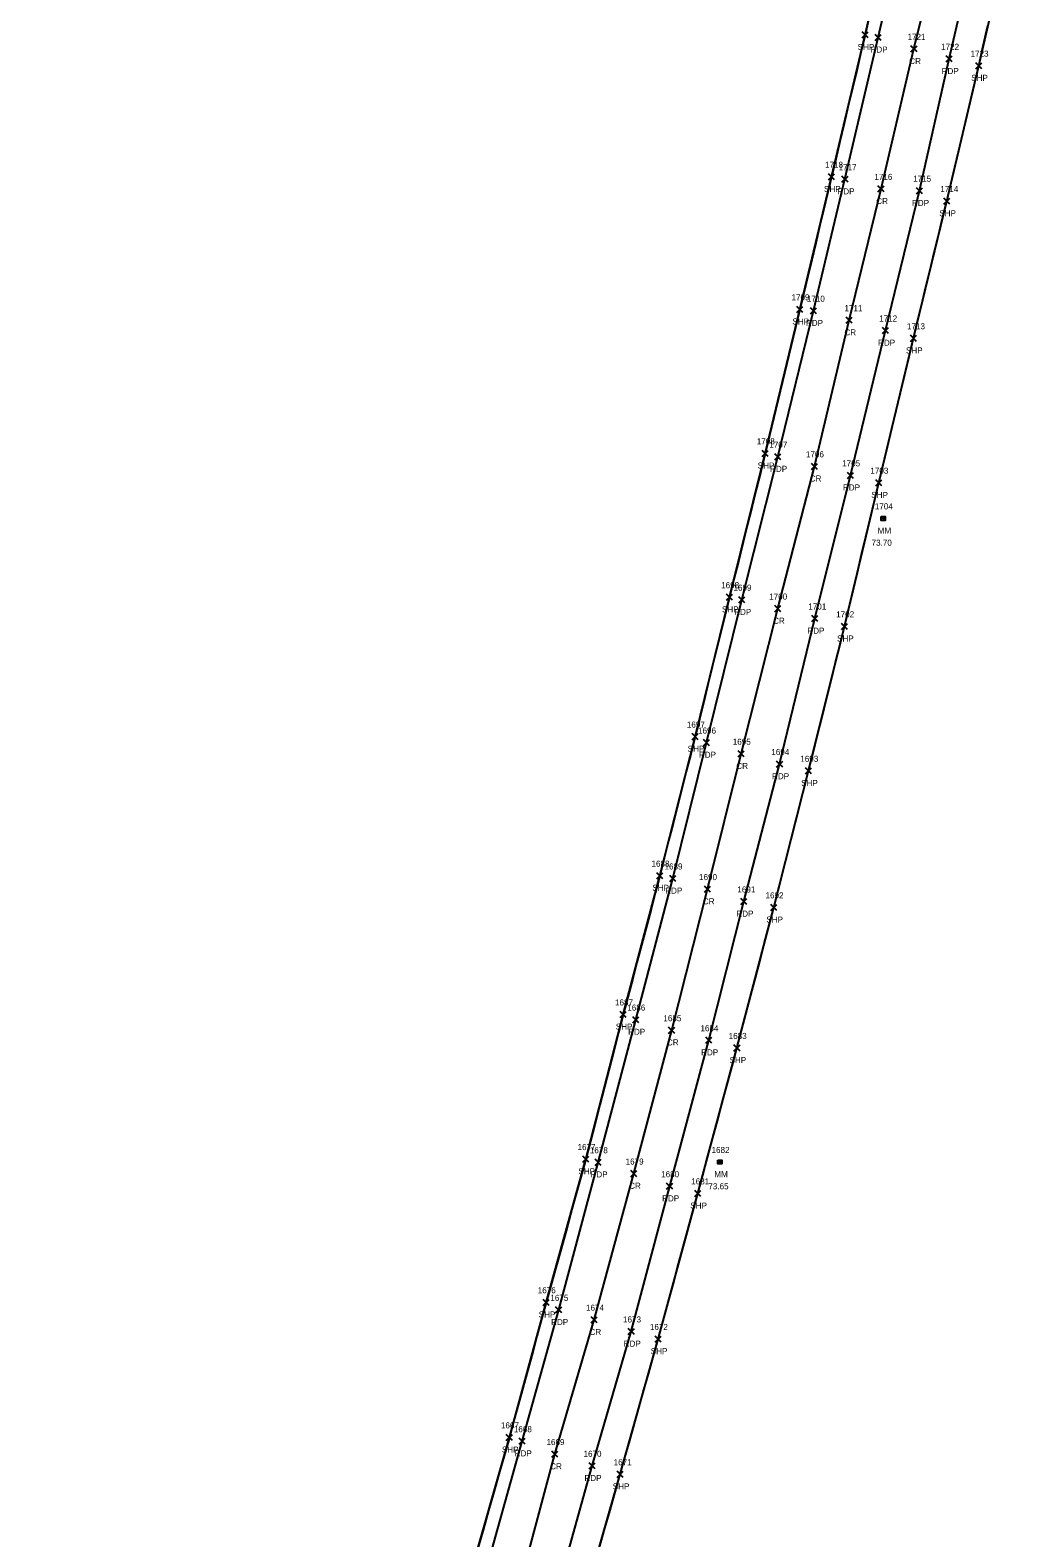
# Model space of a CAD drawing. Extents: x 1688195 to 1692013, y 424605 to 441234.
# Drawn here: x 1690035.6 to 1690361.3, y 433631 to 434129.2 of the extents above; entities that cross this region are included whole.
import ezdxf

# ---------------------------------------------------------------- set-up
doc = ezdxf.new("R2010")
doc.units = 0
for name, color, linetype in [('LSOGP', 7, 'Continuous'), ('P_A', 7, 'Continuous'), ('P_I', 7, 'Continuous'), ('P_TIC', 7, 'Continuous'), ('PET', 7, 'Continuous'), ('PRC', 7, 'Continuous'), ('PSP', 7, 'Continuous'), ('S_A', 7, 'Continuous'), ('S_C', 7, 'Continuous'), ('S_I', 7, 'Continuous'), ('SRM', 7, 'Continuous')]:
    doc.layers.add(name, color=color, linetype=linetype)

msp = doc.modelspace()

# ---------------------------------------------------------------- linework, layer by layer
at = {"layer": 'LSOGP'}
for points in [[(1690312.92, 434133.64), (1690311.54, 434127.65), (1690310.15, 434121.78), (1690308.76, 434115.92), (1690307.37, 434110.05), (1690305.98, 434104.19), (1690304.59, 434098.32), (1690303.19, 434092.46), (1690301.8, 434086.59), (1690299.11, 434075.25), (1690297.8, 434069.77), (1690296.5, 434064.3), (1690295.2, 434058.82), (1690293.89, 434053.35), (1690292.59, 434047.87), (1690291.28, 434042.4), (1690289.98, 434036.92), (1690288.54, 434030.97), (1690287.11, 434025.02), (1690285.67, 434019.07), (1690284.23, 434013.12), (1690282.8, 434007.17), (1690281.36, 434001.22), (1690279.93, 433995.27), (1690278.49, 433989.33), (1690277.02, 433983.38), (1690275.54, 433977.44), (1690274.07, 433971.5), (1690272.59, 433965.56), (1690271.12, 433959.61), (1690269.64, 433953.67), (1690268.17, 433947.73), (1690266.7, 433941.79), (1690265.28, 433936.03), (1690263.86, 433930.27), (1690262.45, 433924.51), (1690261.03, 433918.75), (1690259.61, 433913), (1690258.2, 433907.24), (1690256.78, 433901.48), (1690255.36, 433895.72), (1690253.9, 433889.98), (1690252.44, 433884.24), (1690250.98, 433878.49), (1690249.52, 433872.75), (1690248.06, 433867), (1690246.6, 433861.26), (1690245.14, 433855.52), (1690243.68, 433849.77), (1690242.18, 433844.04), (1690240.67, 433838.3), (1690239.16, 433832.57), (1690237.65, 433826.83), (1690236.14, 433821.1), (1690234.63, 433815.37), (1690233.13, 433809.63), (1690231.62, 433803.9), (1690230.07, 433797.92), (1690228.52, 433791.94), (1690226.98, 433785.97), (1690225.43, 433779.99), (1690223.88, 433774.02), (1690222.33, 433768.04), (1690220.79, 433762.06), (1690219.24, 433756.09), (1690217.6, 433750.17), (1690215.97, 433744.26), (1690214.33, 433738.34), (1690212.69, 433732.43), (1690211.05, 433726.52), (1690209.42, 433720.6), (1690207.78, 433714.69), (1690206.14, 433708.77), (1690204.62, 433703.19), (1690203.1, 433697.61), (1690201.58, 433692.03), (1690200.06, 433686.45), (1690198.53, 433680.86), (1690197.01, 433675.28), (1690195.49, 433669.7), (1690193.97, 433664.12), (1690192.25, 433658.08), (1690190.54, 433652.05), (1690188.82, 433646.02), (1690187.1, 433639.98), (1690185.39, 433633.95), (1690183.67, 433627.91)], [(1690223.85, 433628.22), (1690225.54, 433634.15), (1690227.23, 433640.09), (1690228.92, 433646.02), (1690230.61, 433651.95), (1690232.17, 433657.54), (1690233.74, 433663.13), (1690235.31, 433668.72), (1690236.88, 433674.3), (1690238.45, 433679.89), (1690240.01, 433685.48), (1690241.58, 433691.06), (1690243.15, 433696.65), (1690244.78, 433702.67), (1690246.42, 433708.68), (1690248.05, 433714.69), (1690249.69, 433720.71), (1690251.33, 433726.72), (1690252.96, 433732.74), (1690254.6, 433738.75), (1690256.23, 433744.76), (1690257.85, 433750.77), (1690259.47, 433756.78), (1690261.09, 433762.79), (1690262.71, 433768.8), (1690264.33, 433774.81), (1690265.95, 433780.82), (1690267.57, 433786.83), (1690269.19, 433792.83), (1690270.71, 433798.64), (1690272.23, 433804.45), (1690273.75, 433810.25), (1690275.28, 433816.06), (1690276.8, 433821.86), (1690278.32, 433827.67), (1690279.84, 433833.47), (1690281.36, 433839.28), (1690282.8, 433844.92), (1690284.23, 433850.56), (1690285.67, 433856.2), (1690287.11, 433861.84), (1690288.54, 433867.48), (1690289.98, 433873.13), (1690291.42, 433878.77), (1690292.85, 433884.41), (1690294.34, 433890.38), (1690295.82, 433896.35), (1690297.3, 433902.31), (1690298.79, 433908.28), (1690300.27, 433914.25), (1690301.75, 433920.22), (1690303.24, 433926.19), (1690304.72, 433932.16), (1690306.14, 433938.09), (1690307.55, 433944.02), (1690308.97, 433949.96), (1690310.38, 433955.89), (1690311.8, 433961.82), (1690313.21, 433967.75), (1690314.63, 433973.69), (1690316.05, 433979.62), (1690317.48, 433985.59), (1690318.91, 433991.56), (1690320.34, 433997.52), (1690321.77, 434003.49), (1690323.2, 434009.46), (1690324.63, 434015.43), (1690326.07, 434021.4), (1690327.5, 434027.37), (1690328.87, 434033.04), (1690330.25, 434038.7), (1690331.62, 434044.37), (1690333, 434050.04), (1690334.37, 434055.71), (1690335.75, 434061.37), (1690337.12, 434067.04), (1690338.5, 434072.71), (1690339.82, 434078.3), (1690341.14, 434083.89), (1690342.46, 434089.49), (1690343.78, 434095.08), (1690345.1, 434100.67), (1690346.42, 434106.26), (1690347.74, 434111.86), (1690349.06, 434117.45), (1690350.59, 434124.08), (1690352.13, 434130.71)]]:
    msp.add_lwpolyline(points, dxfattribs=at)
at = {"layer": 'P_TIC'}
for points in [[(1690310.54, 434126.65), (1690312.54, 434128.65)], [(1690312.54, 434126.65), (1690310.54, 434128.65)], [(1690314.83, 434125.81), (1690316.83, 434127.81)], [(1690316.83, 434125.81), (1690314.83, 434127.81)], [(1690326.68, 434122), (1690328.68, 434124)], [(1690328.68, 434122), (1690326.68, 434124)], [(1690338.32, 434118.7), (1690340.32, 434120.7)], [(1690340.32, 434118.7), (1690338.32, 434120.7)], [(1690348.06, 434116.45), (1690350.06, 434118.45)], [(1690350.06, 434116.45), (1690348.06, 434118.45)], [(1690299.41, 434079.72), (1690301.41, 434081.72)], [(1690301.41, 434079.72), (1690299.41, 434081.72)], [(1690303.88, 434078.93), (1690305.88, 434080.93)], [(1690305.88, 434078.93), (1690303.88, 434080.93)], [(1690315.78, 434075.73), (1690317.78, 434077.73)], [(1690317.78, 434075.73), (1690315.78, 434077.73)], [(1690328.53, 434075.11), (1690330.53, 434077.11)], [(1690330.53, 434075.11), (1690328.53, 434077.11)], [(1690337.5, 434071.71), (1690339.5, 434073.71)], [(1690339.5, 434071.71), (1690337.5, 434073.71)], [(1690288.98, 434035.92), (1690290.98, 434037.92)], [(1690290.98, 434035.92), (1690288.98, 434037.92)], [(1690293.48, 434035.45), (1690295.48, 434037.45)], [(1690295.48, 434035.45), (1690293.48, 434037.45)], [(1690305.25, 434032.34), (1690307.25, 434034.34)], [(1690307.25, 434032.34), (1690305.25, 434034.34)], [(1690317.31, 434028.92), (1690319.31, 434030.92)], [(1690319.31, 434028.92), (1690317.31, 434030.92)], [(1690326.5, 434026.37), (1690328.5, 434028.37)], [(1690328.5, 434026.37), (1690326.5, 434028.37)], [(1690277.49, 433988.33), (1690279.49, 433990.33)], [(1690279.49, 433988.33), (1690277.49, 433990.33)], [(1690281.64, 433987.24), (1690283.64, 433989.24)], [(1690283.64, 433987.24), (1690281.64, 433989.24)], [(1690293.79, 433984.05), (1690295.79, 433986.05)], [(1690295.79, 433984.05), (1690293.79, 433986.05)], [(1690305.71, 433981.08), (1690307.71, 433983.08)], [(1690307.71, 433981.08), (1690305.71, 433983.08)], [(1690315.05, 433978.62), (1690317.05, 433980.62)], [(1690317.05, 433978.62), (1690315.05, 433980.62)], [(1690265.7, 433940.79), (1690267.7, 433942.79)], [(1690267.7, 433940.79), (1690265.7, 433942.79)], [(1690269.77, 433939.97), (1690271.77, 433941.97)], [(1690271.77, 433939.97), (1690269.77, 433941.97)], [(1690281.69, 433937.03), (1690283.69, 433939.03)], [(1690283.69, 433937.03), (1690281.69, 433939.03)], [(1690293.95, 433933.74), (1690295.95, 433935.74)], [(1690295.95, 433933.74), (1690293.95, 433935.74)], [(1690303.72, 433931.16), (1690305.72, 433933.16)], [(1690305.72, 433931.16), (1690303.72, 433933.16)], [(1690254.36, 433894.72), (1690256.36, 433896.72)], [(1690256.36, 433894.72), (1690254.36, 433896.72)], [(1690258.12, 433892.75), (1690260.12, 433894.75)], [(1690260.12, 433892.75), (1690258.12, 433894.75)], [(1690269.53, 433889.06), (1690271.53, 433891.06)], [(1690271.53, 433889.06), (1690269.53, 433891.06)], [(1690282.29, 433885.64), (1690284.29, 433887.64)], [(1690284.29, 433885.64), (1690282.29, 433887.64)], [(1690291.85, 433883.41), (1690293.85, 433885.41)], [(1690293.85, 433883.41), (1690291.85, 433885.41)], [(1690242.68, 433848.77), (1690244.68, 433850.77)], [(1690244.68, 433848.77), (1690242.68, 433850.77)], [(1690246.98, 433847.83), (1690248.98, 433849.83)], [(1690248.98, 433847.83), (1690246.98, 433849.83)], [(1690258.48, 433844.32), (1690260.48, 433846.32)], [(1690260.48, 433844.32), (1690258.48, 433846.32)], [(1690270.49, 433840.23), (1690272.49, 433842.23)], [(1690272.49, 433840.23), (1690270.49, 433842.23)], [(1690280.36, 433838.28), (1690282.36, 433840.28)], [(1690282.36, 433838.28), (1690280.36, 433840.28)], [(1690230.62, 433802.9), (1690232.62, 433804.9)], [(1690232.62, 433802.9), (1690230.62, 433804.9)], [(1690234.73, 433801.19), (1690236.73, 433803.19)], [(1690236.73, 433801.19), (1690234.73, 433803.19)], [(1690246.61, 433797.68), (1690248.61, 433799.68)], [(1690248.61, 433797.68), (1690246.61, 433799.68)], [(1690258.85, 433794.38), (1690260.85, 433796.38)], [(1690260.85, 433794.38), (1690258.85, 433796.38)], [(1690268.19, 433791.83), (1690270.19, 433793.83)], [(1690270.19, 433791.83), (1690268.19, 433793.83)], [(1690218.24, 433755.09), (1690220.24, 433757.09)], [(1690220.24, 433755.09), (1690218.24, 433757.09)], [(1690222.3, 433754.05), (1690224.3, 433756.05)], [(1690224.3, 433754.05), (1690222.3, 433756.05)], [(1690234.13, 433750.31), (1690236.13, 433752.31)], [(1690236.13, 433750.31), (1690234.13, 433752.31)], [(1690245.95, 433746.13), (1690247.95, 433748.13)], [(1690247.95, 433746.13), (1690245.95, 433748.13)], [(1690255.23, 433743.76), (1690257.23, 433745.76)], [(1690257.23, 433743.76), (1690255.23, 433745.76)], [(1690205.14, 433707.77), (1690207.14, 433709.77)], [(1690207.14, 433707.77), (1690205.14, 433709.77)], [(1690209.27, 433705.27), (1690211.27, 433707.27)], [(1690211.27, 433705.27), (1690209.27, 433707.27)], [(1690221.03, 433702.01), (1690223.03, 433704.01)], [(1690223.03, 433702.01), (1690221.03, 433704.01)], [(1690233.27, 433698.14), (1690235.27, 433700.14)], [(1690235.27, 433698.14), (1690233.27, 433700.14)], [(1690242.15, 433695.65), (1690244.15, 433697.65)], [(1690244.15, 433695.65), (1690242.15, 433697.65)], [(1690192.97, 433663.12), (1690194.97, 433665.12)], [(1690194.97, 433663.12), (1690192.97, 433665.12)], [(1690197.24, 433661.87), (1690199.24, 433663.87)], [(1690199.24, 433661.87), (1690197.24, 433663.87)], [(1690208.04, 433657.61), (1690210.04, 433659.61)], [(1690210.04, 433657.61), (1690208.04, 433659.61)], [(1690220.31, 433653.72), (1690222.31, 433655.72)], [(1690222.31, 433653.72), (1690220.31, 433655.72)], [(1690229.61, 433650.95), (1690231.61, 433652.95)], [(1690231.61, 433650.95), (1690229.61, 433652.95)]]:
    msp.add_lwpolyline(points, dxfattribs=at)
at = {"layer": 'PET'}
for points in [[(1690039.31, 433141.76), (1690054.57, 433188.01), (1690071.92, 433240.08), (1690086.85, 433287.62), (1690102.26, 433337.25), (1690115.56, 433381.44), (1690131.69, 433432.92), (1690144.59, 433475.99), (1690157.99, 433521.91), (1690171.45, 433568.37), (1690184.55, 433613.87), (1690198.24, 433662.87), (1690210.27, 433706.27), (1690223.3, 433755.05), (1690235.73, 433802.19), (1690247.98, 433848.83), (1690259.12, 433893.75), (1690270.77, 433940.97), (1690282.64, 433988.24), (1690294.48, 434036.45), (1690304.88, 434079.93), (1690315.83, 434126.81), (1690327.01, 434174.5)], [(1690062.43, 433135.09), (1690077.18, 433180.86), (1690093.3, 433230.54), (1690108.95, 433280.36), (1690124.55, 433328.94), (1690138.8, 433375.8), (1690154.11, 433424.03), (1690167.46, 433469.13), (1690181.3, 433514.12), (1690194.42, 433560.22), (1690207.9, 433606.4), (1690221.31, 433654.72), (1690234.27, 433699.14), (1690246.95, 433747.13), (1690259.85, 433795.38), (1690271.49, 433841.23), (1690283.29, 433886.64), (1690294.95, 433934.74), (1690306.71, 433982.08), (1690318.31, 434029.92), (1690329.53, 434076.11), (1690339.32, 434119.7), (1690350.76, 434169.07)]]:
    msp.add_lwpolyline(points, dxfattribs=at)
at = {"layer": 'PRC'}
msp.add_lwpolyline([(1690050.72, 433137.42), (1690066, 433183.94), (1690082.54, 433234.94), (1690098.12, 433283.75), (1690113.76, 433332.8), (1690127.59, 433378.08), (1690142.98, 433428.42), (1690156.2, 433472.69), (1690169.45, 433518.39), (1690182.57, 433564.36), (1690196.15, 433610.32), (1690209.04, 433658.61), (1690222.03, 433703.01), (1690235.13, 433751.31), (1690247.61, 433798.68), (1690259.48, 433845.32), (1690270.53, 433890.06), (1690282.69, 433938.03), (1690294.79, 433985.05), (1690306.25, 434033.34), (1690316.78, 434076.73), (1690327.68, 434123), (1690339.72, 434172)], dxfattribs=at)
at = {"layer": 'PSP'}
for points in [[(1690035.62, 433142.9), (1690050.91, 433189.18), (1690068.06, 433241.76), (1690083.28, 433289.68), (1690098.76, 433338.11), (1690112.2, 433383.07), (1690127.56, 433434.16), (1690141.11, 433477.79), (1690154.03, 433523.19), (1690167.5, 433570.26), (1690180.24, 433615.85), (1690193.97, 433664.12), (1690206.14, 433708.77), (1690219.24, 433756.09), (1690231.62, 433803.9), (1690243.68, 433849.77), (1690255.36, 433895.72), (1690266.7, 433941.79), (1690278.49, 433989.33), (1690289.98, 434036.92), (1690300.41, 434080.72), (1690311.54, 434127.65), (1690322.57, 434175.56)], [(1690072.07, 433131.46), (1690087.47, 433177.91), (1690103.11, 433227.19), (1690119.42, 433278.09), (1690134.51, 433326.59), (1690148.81, 433373.11), (1690163.48, 433420.79), (1690177.06, 433466.35), (1690190.71, 433510.99), (1690203.97, 433557.79), (1690217.09, 433604.48), (1690230.61, 433651.95), (1690243.15, 433696.65), (1690256.23, 433744.76), (1690269.19, 433792.83), (1690281.36, 433839.28), (1690292.85, 433884.41), (1690304.72, 433932.16), (1690316.05, 433979.62), (1690327.5, 434027.37), (1690338.5, 434072.71), (1690349.06, 434117.45), (1690361.33, 434170.48)]]:
    msp.add_lwpolyline(points, dxfattribs=at)
at = {"layer": 'SRM'}
for points in [[(1690316.88, 433968.45), (1690318.13, 433968.45), (1690318.13, 433967.2), (1690316.88, 433967.2)], [(1690262.89, 433755.77), (1690264.14, 433755.77), (1690264.14, 433754.52), (1690262.89, 433754.52)]]:
    msp.add_lwpolyline(points, close=True, dxfattribs=at)
for centre in [(1690317.5, 433967.83), (1690263.52, 433755.15)]:
    msp.add_circle(centre, 0.0833, dxfattribs=at)

# ---------------------------------------------------------------- texts
at = {"layer": 'P_A'}
for s, p in [('SHP', (1690309.07, 434122.65)), ('RDP', (1690313.31, 434121.81)), ('CR', (1690326.11, 434118)), ('RDP', (1690336.81, 434114.7)), ('SHP', (1690346.6, 434112.45)), ('SHP', (1690297.95, 434075.72)), ('RDP', (1690302.37, 434074.93)), ('CR', (1690315.21, 434071.73)), ('RDP', (1690327.01, 434071.11)), ('SHP', (1690336.03, 434067.71)), ('SHP', (1690287.51, 434031.92)), ('RDP', (1690291.97, 434031.45)), ('CR', (1690304.68, 434028.34)), ('RDP', (1690315.8, 434024.92)), ('SHP', (1690325.03, 434022.37)), ('SHP', (1690276.03, 433984.33)), ('RDP', (1690280.12, 433983.24)), ('CR', (1690293.23, 433980.05)), ('RDP', (1690304.2, 433977.08)), ('SHP', (1690313.58, 433974.62)), ('SHP', (1690264.23, 433936.79)), ('RDP', (1690268.26, 433935.97)), ('CR', (1690281.12, 433933.03)), ('RDP', (1690292.44, 433929.74)), ('SHP', (1690302.26, 433927.16)), ('SHP', (1690252.9, 433890.72)), ('RDP', (1690256.61, 433888.75)), ('CR', (1690268.97, 433885.06)), ('RDP', (1690280.77, 433881.64)), ('SHP', (1690290.39, 433879.41)), ('SHP', (1690241.22, 433844.77)), ('RDP', (1690245.47, 433843.83)), ('CR', (1690257.91, 433840.32)), ('RDP', (1690268.98, 433836.23)), ('SHP', (1690278.89, 433834.28)), ('SHP', (1690229.15, 433798.9)), ('RDP', (1690233.22, 433797.19)), ('CR', (1690246.05, 433793.68)), ('RDP', (1690257.34, 433790.38)), ('SHP', (1690266.73, 433787.83)), ('SHP', (1690216.78, 433751.09)), ('RDP', (1690220.79, 433750.05)), ('CR', (1690233.56, 433746.31)), ('RDP', (1690244.44, 433742.13)), ('SHP', (1690253.77, 433739.76)), ('SHP', (1690203.68, 433703.77)), ('RDP', (1690207.76, 433701.27)), ('CR', (1690220.46, 433698.01)), ('RDP', (1690231.76, 433694.14)), ('SHP', (1690240.68, 433691.65)), ('SHP', (1690191.5, 433659.12)), ('RDP', (1690195.73, 433657.87)), ('CR', (1690207.47, 433653.61)), ('RDP', (1690218.79, 433649.72)), ('SHP', (1690228.14, 433646.95))]:
    msp.add_text(s, height=2, dxfattribs=at).set_placement(p)
at = {"layer": 'P_I'}
for s, p in [('1721', (1690325.55, 434126)), ('1722', (1690336.63, 434122.7)), ('1723', (1690346.37, 434120.45)), ('1718', (1690298.29, 434083.72)), ('1717', (1690302.75, 434082.93)), ('1716', (1690314.6, 434079.73)), ('1715', (1690327.4, 434079.11)), ('1714', (1690336.37, 434075.71)), ('1709', (1690287.2, 434039.92)), ('1710', (1690292.27, 434039.45)), ('1711', (1690304.69, 434036.34)), ('1712', (1690316.18, 434032.92)), ('1713', (1690325.37, 434030.37)), ('1708', (1690275.72, 433992.33)), ('1707', (1690279.87, 433991.24)), ('1706', (1690291.97, 433988.05)), ('1705', (1690303.94, 433985.08)), ('1703', (1690313.27, 433982.62)), ('1698', (1690263.95, 433944.79)), ('1699', (1690268.03, 433943.97)), ('1700', (1690279.83, 433941.03)), ('1701', (1690292.74, 433937.74)), ('1702', (1690301.95, 433935.16)), ('1697', (1690252.62, 433898.72)), ('1696', (1690256.32, 433896.75)), ('1695', (1690267.79, 433893.06)), ('1694', (1690280.54, 433889.64)), ('1693', (1690290.11, 433887.41)), ('1688', (1690240.94, 433852.77)), ('1689', (1690245.24, 433851.83)), ('1690', (1690256.65, 433848.32)), ('1691', (1690269.32, 433844.23)), ('1692', (1690278.62, 433842.28)), ('1687', (1690228.88, 433806.9)), ('1686', (1690232.94, 433805.19)), ('1685', (1690244.87, 433801.68)), ('1684', (1690257.11, 433798.38)), ('1683', (1690266.45, 433795.83)), ('1677', (1690216.5, 433759.09)), ('1678', (1690220.56, 433758.05)), ('1679', (1690232.38, 433754.31)), ('1680', (1690244.13, 433750.13)), ('1681', (1690254.06, 433747.76)), ('1676', (1690203.35, 433711.77)), ('1675', (1690207.53, 433709.27)), ('1674', (1690219.29, 433706.01)), ('1673', (1690231.53, 433702.14)), ('1672', (1690240.41, 433699.65)), ('1667', (1690191.18, 433667.12)), ('1668', (1690195.45, 433665.87)), ('1669', (1690206.24, 433661.61)), ('1670', (1690218.48, 433657.72)), ('1671', (1690228.43, 433654.95))]:
    msp.add_text(s, height=2, dxfattribs=at).set_placement(p)
at = {"layer": 'S_A'}
for p in [(1690315.69, 433962.83), (1690261.71, 433750.15)]:
    msp.add_text('MM', height=2, dxfattribs=at).set_placement(p)
at = {"layer": 'S_C'}
for s, p in [('73.70', (1690313.67, 433958.83)), ('73.65', (1690259.72, 433746.15))]:
    msp.add_text(s, height=2, dxfattribs=at).set_placement(p)
at = {"layer": 'S_I'}
for s, p in [('1704', (1690314.73, 433970.83)), ('1682', (1690260.78, 433758.15))]:
    msp.add_text(s, height=2, dxfattribs=at).set_placement(p)

doc.saveas('drawing.dxf')
